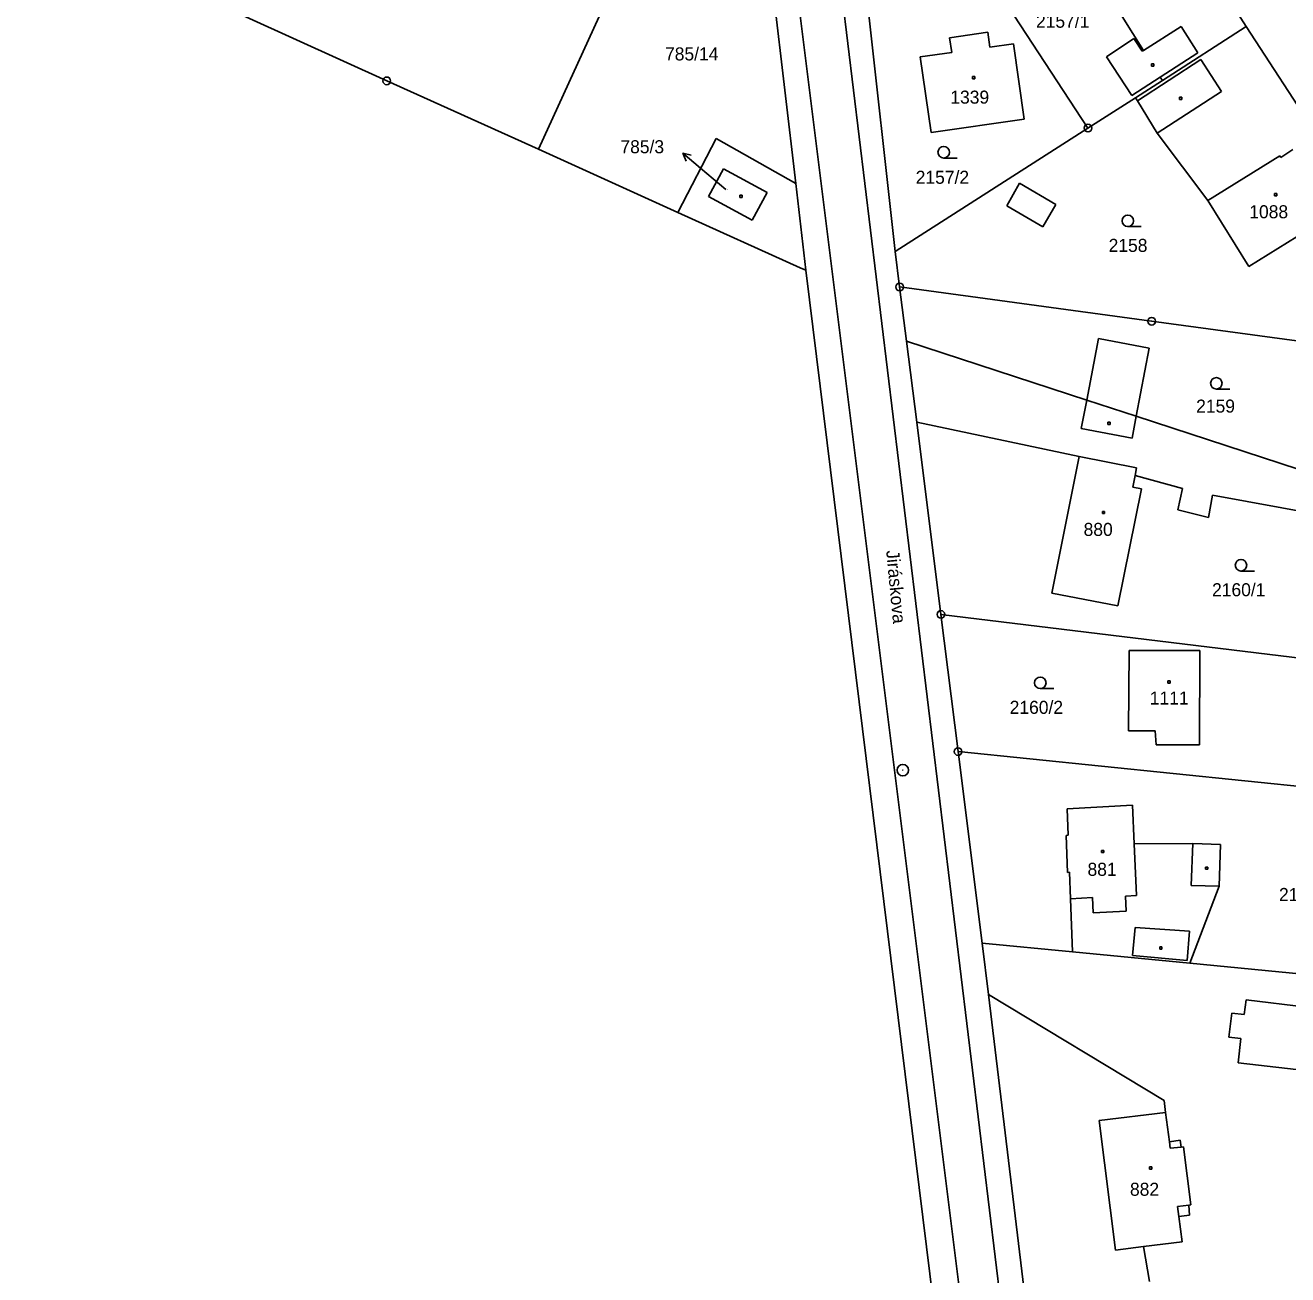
# Model space of a CAD drawing. Extents: x -795483 to -789093, y -1112258 to -1108741.
# Drawn here: x -791869.6 to -791705.2, y -1111421 to -1111258.2 of the extents above; entities that cross this region are included whole.
import ezdxf

# ---------------------------------------------------------------- set-up
doc = ezdxf.new("R2010")
doc.units = 0
for name, color, linetype in [('Komunikace', 7, 'Continuous'), ('Vrstva 1', 7, 'Continuous'), ('Vrstva 14', 7, 'Continuous'), ('Vrstva 15', 7, 'Continuous'), ('Vrstva 16', 7, 'Continuous'), ('Vrstva 2', 7, 'Continuous'), ('Vrstva 23', 7, 'Continuous'), ('Vrstva 25', 7, 'Continuous'), ('Vrstva 28', 7, 'Continuous'), ('Vrstva 38', 7, 'Continuous'), ('Vrstva 4', 7, 'Continuous')]:
    doc.layers.add(name, color=color, linetype=linetype)

msp = doc.modelspace()

# ---------------------------------------------------------------- linework, layer by layer
at = {"layer": 'Komunikace'}
msp.add_line((-791778.35, -1111279.62), (-791781.67, -1111276.82), dxfattribs=at)
at = {"layer": 'Vrstva 1'}
for p, q in [((-791726.74, -1111233.13), (-791710.58, -1111258.39)), ((-791769.26, -1111278.81), (-791773.96, -1111238.71)), ((-791747.66, -1111246.51), (-791731.19, -1111271.6)), ((-791791.42, -1111249.5), (-791802.74, -1111274.36)), ((-791728.5, -1111254.26), (-791723.96, -1111261.48)), ((-791760.01, -1111254.41), (-791756.3, -1111287.69)), ((-791749.21, -1111259.84), (-791744.22, -1111259.11)), ((-791744.22, -1111259.11), (-791743.96, -1111261.04)), ((-791710.58, -1111258.39), (-791721.5, -1111265.39)), ((-791710.58, -1111258.39), (-791698.34, -1111277.22)), ((-791748.93, -1111261.76), (-791749.21, -1111259.84)), ((-791743.96, -1111261.04), (-791740.91, -1111260.61)), ((-791740.91, -1111260.61), (-791739.51, -1111270.45)), ((-791725.2, -1111259.94), (-791728.78, -1111262.3)), ((-791725.2, -1111259.94), (-791724.14, -1111261.6)), ((-791753.03, -1111262.33), (-791748.93, -1111261.76)), ((-791751.61, -1111272.17), (-791753.03, -1111262.33)), ((-791728.78, -1111262.3), (-791725.49, -1111267.37)), ((-791724.14, -1111261.6), (-791723.96, -1111261.48)), ((-791725.49, -1111267.37), (-791721.77, -1111264.96)), ((-791721.5, -1111265.39), (-791725.01, -1111267.65)), ((-791721.77, -1111264.96), (-791721.5, -1111265.39)), ((-791725.01, -1111267.65), (-791731.19, -1111271.6)), ((-791725.01, -1111267.65), (-791724.76, -1111268.05)), ((-791724.76, -1111268.05), (-791722.16, -1111272.25)), ((-791739.51, -1111270.45), (-791751.61, -1111272.17)), ((-791731.19, -1111271.6), (-791756.3, -1111287.69)), ((-791722.16, -1111272.25), (-791715.59, -1111281.05)), ((-791784.62, -1111282.6), (-791779.63, -1111272.96)), ((-791779.63, -1111272.96), (-791769.26, -1111278.81)), ((-791767.93, -1111290.13), (-791769.26, -1111278.81)), ((-791715.59, -1111281.05), (-791710.22, -1111289.63)), ((-791700.74, -1111283.7), (-791710.22, -1111289.63)), ((-791756.3, -1111287.69), (-791755.72, -1111292.3)), ((-791755.72, -1111292.3), (-791754.83, -1111299.36)), ((-791722.9, -1111296.76), (-791755.72, -1111292.3)), ((-791694.78, -1111300.58), (-791722.9, -1111296.76)), ((-791731.35, -1111307.03), (-791754.83, -1111299.36)), ((-791754.83, -1111299.36), (-791753.5, -1111309.92)), ((-791724.9, -1111309.14), (-791731.35, -1111307.03)), ((-791753.5, -1111309.92), (-791750.35, -1111334.96)), ((-791732.33, -1111314.39), (-791753.5, -1111309.92)), ((-791696.27, -1111318.5), (-791724.9, -1111309.14)), ((-791735.88, -1111332.17), (-791732.33, -1111314.39)), ((-791725.05, -1111316.86), (-791725.35, -1111318.37)), ((-791725.35, -1111318.37), (-791724.24, -1111318.59)), ((-791718.9, -1111318.56), (-791725.05, -1111316.86)), ((-791724.24, -1111318.59), (-791727.31, -1111333.83)), ((-791719.5, -1111321.35), (-791718.9, -1111318.56)), ((-791714.96, -1111319.41), (-791715.5, -1111322.32)), ((-791696.63, -1111322.78), (-791714.96, -1111319.41)), ((-791715.5, -1111322.32), (-791719.5, -1111321.35)), ((-791727.31, -1111333.83), (-791735.88, -1111332.17)), ((-791750.35, -1111334.96), (-791748.11, -1111352.82)), ((-791698.12, -1111341.31), (-791750.35, -1111334.96)), ((-791725.82, -1111339.64), (-791725.92, -1111350.12)), ((-791725.82, -1111339.64), (-791716.6, -1111339.65)), ((-791716.6, -1111339.65), (-791716.67, -1111351.93)), ((-791722.42, -1111350.14), (-791725.92, -1111350.12)), ((-791722.33, -1111351.96), (-791722.42, -1111350.14)), ((-791748.11, -1111352.82), (-791744.97, -1111377.78)), ((-791699.4, -1111357.8), (-791748.11, -1111352.82)), ((-791716.67, -1111351.93), (-791722.33, -1111351.96)), ((-791733.88, -1111360.3), (-791725.39, -1111359.82)), ((-791733.76, -1111363.73), (-791733.88, -1111360.3)), ((-791725.39, -1111359.82), (-791725.17, -1111364.82)), ((-791734.04, -1111363.74), (-791733.76, -1111363.73)), ((-791733.87, -1111368.56), (-791734.04, -1111363.74)), ((-791725.17, -1111364.82), (-791717.53, -1111364.78)), ((-791717.53, -1111364.78), (-791713.95, -1111364.92)), ((-791713.95, -1111364.92), (-791714.12, -1111370.35)), ((-791733.59, -1111368.55), (-791733.87, -1111368.56)), ((-791733.47, -1111371.99), (-791733.59, -1111368.55)), ((-791714.12, -1111370.35), (-791717.91, -1111380.39)), ((-791733.22, -1111378.91), (-791733.47, -1111371.99)), ((-791733.22, -1111378.91), (-791744.97, -1111377.78)), ((-791744.97, -1111377.78), (-791744.16, -1111384.45)), ((-791717.91, -1111380.39), (-791733.22, -1111378.91)), ((-791692.14, -1111382.88), (-791717.91, -1111380.39)), ((-791744.16, -1111384.45), (-791721.25, -1111398.28)), ((-791744.16, -1111384.45), (-791739.38, -1111424.13)), ((-791721.25, -1111398.28), (-791721.11, -1111399.82)), ((-791721.11, -1111399.82), (-791720.57, -1111403.64)), ((-791720.57, -1111403.64), (-791719.19, -1111403.46)), ((-791719.19, -1111403.46), (-791719.07, -1111404.35)), ((-791719.07, -1111404.35), (-791718.74, -1111404.31)), ((-791718.74, -1111404.31), (-791717.78, -1111411.88)), ((-791717.78, -1111411.88), (-791718.05, -1111411.91)), ((-791718.05, -1111411.91), (-791717.96, -1111413.22)), ((-791717.96, -1111413.22), (-791719.35, -1111413.39)), ((-791719.35, -1111413.39), (-791718.92, -1111416.68)), ((-791718.92, -1111416.68), (-791723.95, -1111417.3)), ((-791723.95, -1111417.3), (-791723.17, -1111421.87))]:
    msp.add_line(p, q, dxfattribs=at)
at = {"layer": 'Vrstva 16'}
for p, q in [((-791781.67, -1111276.82), (-791783.96, -1111274.88)), ((-791783.96, -1111274.88), (-791783.52, -1111275.91)), ((-791783.96, -1111274.88), (-791782.88, -1111275.15))]:
    msp.add_line(p, q, dxfattribs=at)
at = {"layer": 'Vrstva 2'}
for p, q in [((-791769.19, -1111205.07), (-791734.76, -1111488.89)), ((-791739.62, -1111489.46), (-791769.3, -1111251.83)), ((-791723.96, -1111261.48), (-791719.07, -1111258.35)), ((-791719.07, -1111258.35), (-791716.89, -1111261.78)), ((-791716.89, -1111261.78), (-791721.77, -1111264.96)), ((-791724.76, -1111268.05), (-791716.5, -1111262.66)), ((-791716.5, -1111262.66), (-791713.78, -1111266.83)), ((-791713.78, -1111266.83), (-791722.16, -1111272.25)), ((-791715.59, -1111281.05), (-791706.21, -1111275.22)), ((-791706.21, -1111275.22), (-791706.08, -1111275.43)), ((-791706.08, -1111275.43), (-791704.49, -1111274.4)), ((-791780.62, -1111280.52), (-791778.65, -1111276.9)), ((-791778.65, -1111276.9), (-791772.98, -1111279.99)), ((-791741.77, -1111281.74), (-791740.12, -1111278.79)), ((-791740.12, -1111278.79), (-791735.39, -1111281.55)), ((-791774.95, -1111283.61), (-791780.62, -1111280.52)), ((-791772.98, -1111279.99), (-791774.95, -1111283.61)), ((-791737.05, -1111284.45), (-791741.77, -1111281.74)), ((-791735.39, -1111281.55), (-791737.05, -1111284.45)), ((-791731.35, -1111307.03), (-791729.81, -1111299)), ((-791729.81, -1111299), (-791723.2, -1111300.27)), ((-791723.2, -1111300.27), (-791724.9, -1111309.14)), ((-791731.35, -1111307.03), (-791732.06, -1111310.73)), ((-791725.45, -1111312), (-791724.9, -1111309.14)), ((-791732.06, -1111310.73), (-791725.45, -1111312)), ((-791732.33, -1111314.39), (-791724.85, -1111315.88)), ((-791724.85, -1111315.88), (-791725.05, -1111316.86)), ((-791724.88, -1111371.57), (-791725.17, -1111364.82)), ((-791717.53, -1111364.78), (-791717.75, -1111370.25)), ((-791717.75, -1111370.25), (-791714.12, -1111370.35)), ((-791733.47, -1111371.99), (-791730.61, -1111371.85)), ((-791730.61, -1111371.85), (-791730.52, -1111373.83)), ((-791726.31, -1111371.64), (-791724.88, -1111371.57)), ((-791726.21, -1111373.61), (-791726.31, -1111371.64)), ((-791730.52, -1111373.83), (-791726.21, -1111373.61)), ((-791725.39, -1111379.37), (-791725.04, -1111375.76)), ((-791725.04, -1111375.76), (-791717.97, -1111376.22)), ((-791717.97, -1111376.22), (-791718.29, -1111380.05)), ((-791725.39, -1111379.37), (-791718.29, -1111380.05)), ((-791710.84, -1111387.09), (-791710.6, -1111385.16)), ((-791710.6, -1111385.16), (-791702.74, -1111386.13)), ((-791712.85, -1111390.01), (-791712.45, -1111386.89)), ((-791712.45, -1111386.89), (-791710.84, -1111387.09)), ((-791711.26, -1111390.19), (-791712.85, -1111390.01)), ((-791711.62, -1111393.38), (-791711.26, -1111390.19)), ((-791691.55, -1111395.65), (-791711.62, -1111393.38)), ((-791721.11, -1111399.82), (-791729.72, -1111400.87)), ((-791729.72, -1111400.87), (-791727.61, -1111417.77)), ((-791720.5, -1111404.49), (-791720.57, -1111403.64)), ((-791719.07, -1111404.35), (-791720.5, -1111404.49)), ((-791719.52, -1111412.1), (-791718.05, -1111411.91)), ((-791719.35, -1111413.39), (-791719.52, -1111412.1)), ((-791727.61, -1111417.77), (-791723.95, -1111417.3))]:
    msp.add_line(p, q, dxfattribs=at)
at = {"layer": 'Vrstva 23'}
for p, q in [((-791749.98, -1111275.5), (-791748.23, -1111275.5)), ((-791726, -1111284.44), (-791724.25, -1111284.44)), ((-791714.47, -1111305.6), (-791712.72, -1111305.6)), ((-791711.26, -1111329.3), (-791709.51, -1111329.3)), ((-791737.4, -1111344.62), (-791735.65, -1111344.62))]:
    msp.add_line(p, q, dxfattribs=at)
for centre in [(-791749.98, -1111274.75), (-791726, -1111283.69), (-791714.47, -1111304.85), (-791711.26, -1111328.55), (-791737.4, -1111343.87)]:
    msp.add_circle(centre, 0.75, dxfattribs=at)
at = {"layer": 'Vrstva 25'}
for p, q in [((-791722.91, -1111263.23), (-791722.61, -1111263.23)), ((-791722.91, -1111263.53), (-791722.91, -1111263.23)), ((-791722.61, -1111263.53), (-791722.91, -1111263.53)), ((-791722.61, -1111263.23), (-791722.61, -1111263.53)), ((-791746.24, -1111264.87), (-791745.94, -1111264.87)), ((-791746.24, -1111265.17), (-791746.24, -1111264.87)), ((-791745.94, -1111265.17), (-791746.24, -1111265.17)), ((-791745.94, -1111264.87), (-791745.94, -1111265.17)), ((-791719.25, -1111267.57), (-791718.95, -1111267.57)), ((-791719.25, -1111267.87), (-791719.25, -1111267.57)), ((-791718.95, -1111267.87), (-791719.25, -1111267.87)), ((-791718.95, -1111267.57), (-791718.95, -1111267.87)), ((-791776.52, -1111280.34), (-791776.22, -1111280.34)), ((-791776.52, -1111280.64), (-791776.52, -1111280.34)), ((-791776.22, -1111280.34), (-791776.22, -1111280.64)), ((-791706.88, -1111280.14), (-791706.58, -1111280.14)), ((-791706.88, -1111280.44), (-791706.88, -1111280.14)), ((-791706.58, -1111280.44), (-791706.88, -1111280.44)), ((-791706.58, -1111280.14), (-791706.58, -1111280.44)), ((-791776.22, -1111280.64), (-791776.52, -1111280.64)), ((-791728.59, -1111309.92), (-791728.29, -1111309.92)), ((-791728.59, -1111310.22), (-791728.59, -1111309.92)), ((-791728.29, -1111309.92), (-791728.29, -1111310.22)), ((-791728.29, -1111310.22), (-791728.59, -1111310.22)), ((-791729.32, -1111321.53), (-791729.02, -1111321.53)), ((-791729.32, -1111321.83), (-791729.32, -1111321.53)), ((-791729.02, -1111321.53), (-791729.02, -1111321.83)), ((-791729.02, -1111321.83), (-791729.32, -1111321.83)), ((-791720.77, -1111343.62), (-791720.47, -1111343.62)), ((-791720.77, -1111343.92), (-791720.77, -1111343.62)), ((-791720.47, -1111343.92), (-791720.77, -1111343.92)), ((-791720.47, -1111343.62), (-791720.47, -1111343.92)), ((-791729.41, -1111365.69), (-791729.11, -1111365.69)), ((-791729.41, -1111365.99), (-791729.41, -1111365.69)), ((-791729.11, -1111365.99), (-791729.41, -1111365.99)), ((-791729.11, -1111365.69), (-791729.11, -1111365.99)), ((-791715.9, -1111367.86), (-791715.6, -1111367.86)), ((-791715.9, -1111368.16), (-791715.9, -1111367.86)), ((-791715.6, -1111368.16), (-791715.9, -1111368.16)), ((-791715.6, -1111367.86), (-791715.6, -1111368.16)), ((-791721.85, -1111378.25), (-791721.55, -1111378.25)), ((-791721.85, -1111378.55), (-791721.85, -1111378.25)), ((-791721.55, -1111378.55), (-791721.85, -1111378.55)), ((-791721.55, -1111378.25), (-791721.55, -1111378.55)), ((-791723.17, -1111406.91), (-791722.87, -1111406.91)), ((-791723.17, -1111407.21), (-791723.17, -1111406.91)), ((-791722.87, -1111406.91), (-791722.87, -1111407.21)), ((-791722.87, -1111407.21), (-791723.17, -1111407.21))]:
    msp.add_line(p, q, dxfattribs=at)
at = {"layer": 'Vrstva 28'}
for centre, radius in [((-791822.52, -1111265.45), 0.5), ((-791822.52, -1111265.45), 0.01), ((-791731.19, -1111271.6), 0.5), ((-791731.19, -1111271.6), 0.01), ((-791755.72, -1111292.3), 0.5), ((-791755.72, -1111292.3), 0.01), ((-791722.9, -1111296.76), 0.5), ((-791722.9, -1111296.76), 0.01), ((-791750.35, -1111334.96), 0.5), ((-791750.35, -1111334.96), 0.01), ((-791748.11, -1111352.82), 0.5), ((-791748.11, -1111352.82), 0.01), ((-791755.31, -1111355.24), 0.75), ((-791755.31, -1111355.24), 0.01)]:
    msp.add_circle(centre, radius, dxfattribs=at)
at = {"layer": 'Vrstva 4'}
for p, q in [((-791822.52, -1111265.45), (-791869.61, -1111243.92)), ((-791822.52, -1111265.45), (-791802.74, -1111274.36)), ((-791784.62, -1111282.6), (-791802.74, -1111274.36)), ((-791768.68, -1111289.81), (-791784.62, -1111282.6)), ((-791767.93, -1111290.13), (-791768.68, -1111289.81)), ((-791738.46, -1111528.89), (-791767.93, -1111290.13))]:
    msp.add_line(p, q, dxfattribs=at)

# ---------------------------------------------------------------- texts
at = {"layer": 'Vrstva 14'}
for s, p in [('2157/1', (-791737.96, -1111258.53)), ('2157/2', (-791753.63, -1111278.86)), ('2158', (-791728.5, -1111287.73)), ('2159', (-791717.1, -1111308.67)), ('2160/1', (-791715.03, -1111332.59)), ('2160/2', (-791741.39, -1111347.91)), ('2164', (-791706.31, -1111372.29))]:
    msp.add_text(s, height=1.7, dxfattribs=at).set_placement(p)
at = {"layer": 'Vrstva 15'}
for s, height, p in [('785/14', 1.7, (-791786.28, -1111262.79)), ('1339', 1.7, (-791749.12, -1111268.42)), ('785/3', 0.1, (-791778.35, -1111279.62)), ('1088', 1.7, (-791710.18, -1111283.35)), ('880', 1.7, (-791731.76, -1111324.73)), ('1111', 1.7, (-791723.14, -1111346.7)), ('881', 1.7, (-791731.25, -1111369.01)), ('882', 1.7, (-791725.72, -1111410.69))]:
    msp.add_text(s, height=height, dxfattribs=at).set_placement(p)
at = {"layer": 'Vrstva 16'}
msp.add_text('785/3', height=1.7, dxfattribs=at).set_placement((-791792.09, -1111274.88))
at = {"layer": 'Vrstva 38'}
msp.add_text('Jiráskova', height=1.7, rotation=275.453, dxfattribs=at).set_placement((-791757.48, -1111326.66))

doc.saveas('drawing.dxf')
